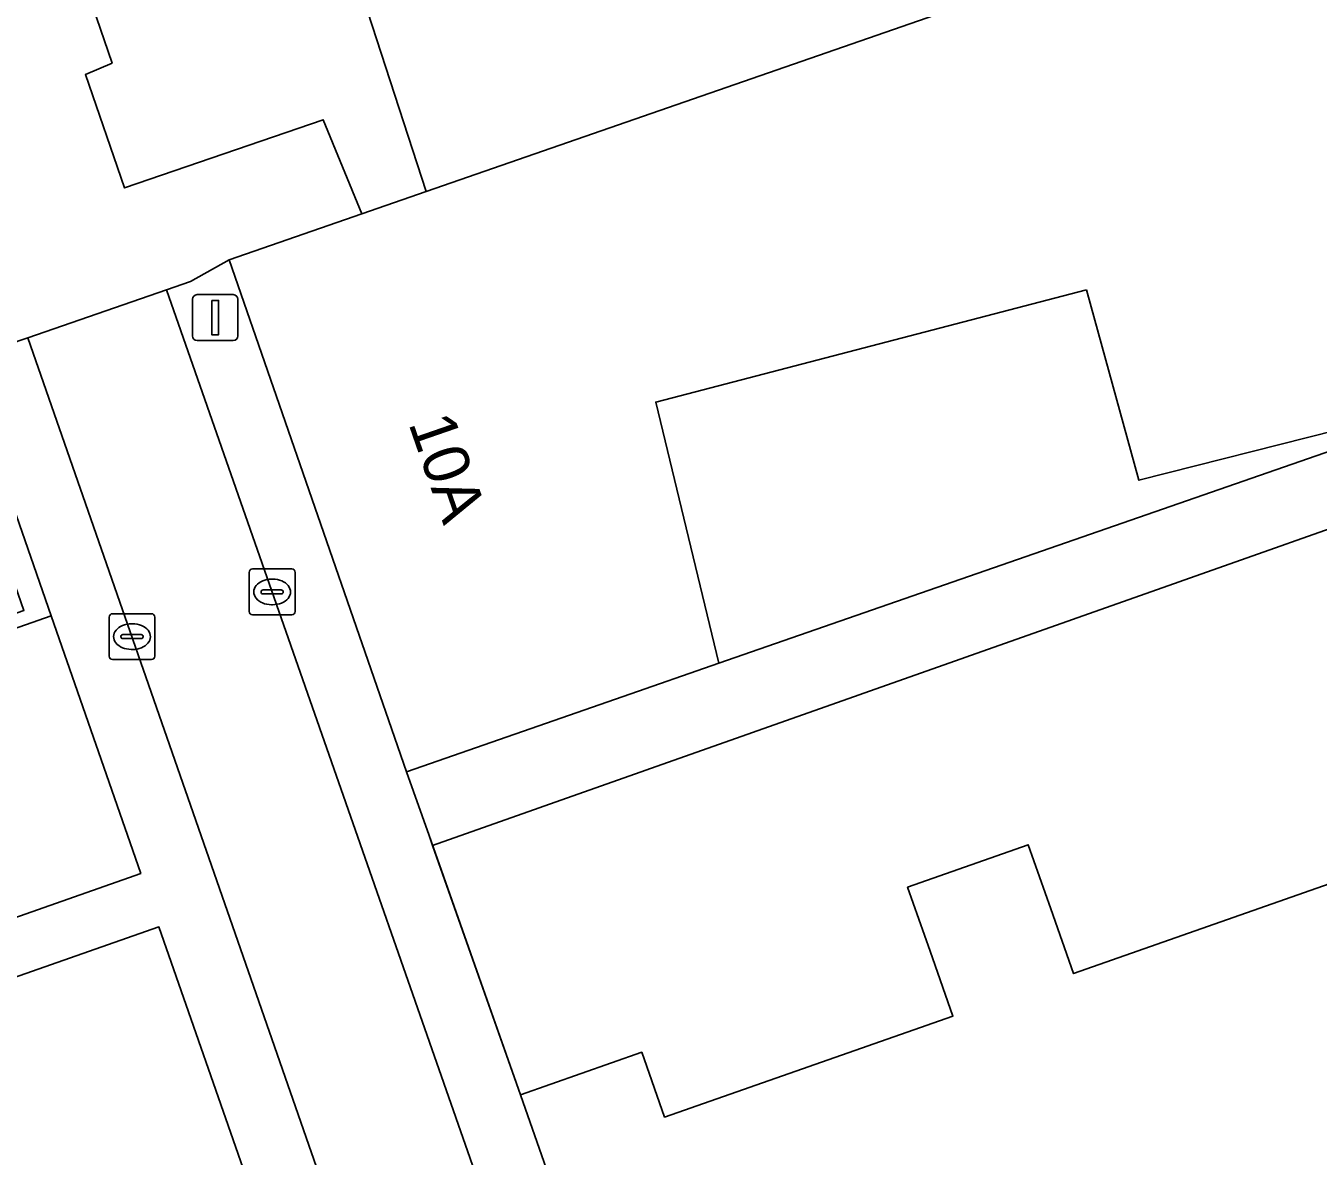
# Model space of a CAD drawing. Extents: x 159371 to 159986, y 382987 to 383597.
# Drawn here: x 159635.1 to 159663.28, y 383315.4 to 383340.04 of the extents above; entities that cross this region are included whole.
import ezdxf

# ---------------------------------------------------------------- set-up
doc = ezdxf.new("R2010")
doc.units = 0
for name, color, linetype in [('IMGEO_Erf', 7, 'Continuous'), ('IMGEO_Groenvoorziening', 7, 'Continuous'), ('IMGEO_Kolk', 7, 'Continuous'), ('IMGEO_Lichtmast', 7, 'Continuous'), ('IMGEO_Muur', 7, 'Continuous'), ('IMGEO_Pand', 7, 'Continuous'), ('IMGEO_Pand_nummerreeks', 7, 'Continuous'), ('IMGEO_Rijbaan_lokaal_open', 7, 'Continuous'), ('IMGEO_Terreindeel_gesloten', 7, 'Continuous'), ('IMGEO_Voetpad_open', 7, 'Continuous')]:
    doc.layers.add(name, color=color, linetype=linetype)

msp = doc.modelspace()

# ---------------------------------------------------------------- linework, layer by layer
at = {"layer": 'IMGEO_Erf'}
for points in [[(159681.296, 383335.353), (159643.966, 383322.174), (159645.886, 383316.734), (159648.529, 383317.662), (159649.026, 383316.247), (159655.31, 383318.452), (159654.813, 383319.867), (159654.323, 383321.261), (159656.956, 383322.186), (159657.446, 383320.791), (159657.943, 383319.376), (159664.368, 383321.63)], [(159633.525, 383310.811), (159640.34, 383313.197), (159639.844, 383314.612), (159639.998, 383314.666), (159638.001, 383320.394), (159611.994, 383311.273)]]:
    msp.add_lwpolyline(points, dxfattribs=at)
msp.add_lwpolyline([(159658.222, 383334.284), (159648.831, 383331.841), (159650.209, 383326.145), (159667.985, 383332.318), (159659.367, 383330.135)], close=True, dxfattribs=at)
at = {"layer": 'IMGEO_Groenvoorziening'}
msp.add_lwpolyline([(159634.849, 383345.441), (159636.979, 383339.231), (159636.397, 383338.982), (159637.249, 383336.509), (159641.583, 383337.997), (159642.421, 383335.945), (159643.825, 383336.433), (159639.809, 383348.793), (159650.451, 383352.464), (159648.673, 383358.7), (159660.333, 383361.889), (159659.23, 383366.272), (159646.569, 383362.986), (159645.066, 383369.122), (159646.091, 383369.372), (159643.576, 383379.146), (159638.181, 383377.778), (159637.233, 383377.7), (159639.388, 383369.792), (159627.787, 383366.742)], dxfattribs=at)
at = {"layer": 'IMGEO_Kolk'}
for p, q in [((159640.043, 383328.2), (159640.895, 383328.2)), ((159639.968, 383327.274), (159639.968, 383328.126)), ((159640.456, 383327.98), (159640.481, 383327.98)), ((159640.969, 383328.126), (159640.969, 383327.274)), ((159640.227, 383327.694), (159640.227, 383327.706)), ((159640.665, 383327.657), (159640.267, 383327.657)), ((159640.27, 383327.743), (159640.668, 383327.743)), ((159640.711, 383327.706), (159640.711, 383327.694)), ((159640.479, 383327.42), (159640.454, 383327.42)), ((159636.912, 383326.299), (159636.912, 383327.151)), ((159636.987, 383327.225), (159637.839, 383327.225)), ((159637.913, 383327.151), (159637.913, 383326.299)), ((159640.895, 383327.2), (159640.043, 383327.2)), ((159637.214, 383326.768), (159637.612, 383326.768)), ((159637.4, 383327.005), (159637.425, 383327.005)), ((159637.171, 383326.719), (159637.171, 383326.731)), ((159637.609, 383326.682), (159637.211, 383326.682)), ((159637.655, 383326.731), (159637.655, 383326.719)), ((159637.839, 383326.225), (159636.987, 383326.225)), ((159637.423, 383326.445), (159637.398, 383326.445))]:
    msp.add_line(p, q, dxfattribs=at)
for points in [[(159640.043, 383328.2), (159640.895, 383328.2)], [(159639.968, 383327.274), (159639.968, 383328.126)], [(159640.969, 383328.126), (159640.969, 383327.274)], [(159636.912, 383326.299), (159636.912, 383327.151)], [(159636.987, 383327.225), (159637.839, 383327.225)], [(159637.913, 383327.151), (159637.913, 383326.299)], [(159640.895, 383327.2), (159640.043, 383327.2)], [(159637.839, 383326.225), (159636.987, 383326.225)]]:
    msp.add_lwpolyline(points, dxfattribs=at)
for centre, radius, start, end in [((159640.045, 383328.124), 0.0765, 91.552, 178.448), ((159640.045, 383328.124), 0.0765, 91.552, 178.448), ((159640.893, 383328.124), 0.0765, 1.552, 88.448), ((159640.893, 383328.124), 0.0765, 1.552, 88.448), ((159640.267, 383327.703), 0.0403, 85.8775, 175.7526), ((159640.264, 383327.693), 0.0366, 178.938, 274.7102), ((159640.668, 383327.7), 0.043, 264.8664, 352.4533), ((159640.672, 383327.705), 0.0386, 1.7309, 96.639), ((159636.989, 383327.149), 0.0765, 91.552, 178.448), ((159636.989, 383327.149), 0.0765, 91.552, 178.448), ((159637.837, 383327.149), 0.0765, 1.552, 88.448), ((159637.837, 383327.149), 0.0765, 1.552, 88.448), ((159640.045, 383327.276), 0.0765, 181.552, 268.448), ((159640.045, 383327.276), 0.0765, 181.552, 268.448), ((159640.893, 383327.276), 0.0765, 271.552, 358.448), ((159640.893, 383327.276), 0.0765, 271.552, 358.448), ((159637.211, 383326.728), 0.0403, 85.8775, 175.7526), ((159637.616, 383326.73), 0.0386, 1.7309, 96.639), ((159637.208, 383326.718), 0.0366, 178.938, 274.7102), ((159637.612, 383326.725), 0.043, 264.8664, 352.4533), ((159636.989, 383326.301), 0.0765, 181.552, 268.448), ((159636.989, 383326.301), 0.0765, 181.552, 268.448), ((159637.837, 383326.301), 0.0765, 271.552, 358.448), ((159637.837, 383326.301), 0.0765, 271.552, 358.448)]:
    msp.add_arc(centre, radius, start, end, dxfattribs=at)
for centre, major_axis, ratio, start_param, end_param in [((159640.455, 383327.7), (-0.387, 0.002), 0.722429, 4.712389, 7.853982), ((159640.48, 383327.7), (-0.39, 0.002), 0.717154, 1.570796, 4.712389), ((159637.399, 383326.725), (-0.387, 0.002), 0.722429, 4.712389, 7.853982), ((159637.424, 383326.725), (-0.39, 0.002), 0.717154, 1.570796, 4.712389)]:
    msp.add_ellipse(centre, major_axis=major_axis, ratio=ratio, start_param=start_param, end_param=end_param, dxfattribs=at)
at = {"layer": 'IMGEO_Lichtmast'}
for p, q in [((159638.732, 383333.282), (159638.732, 383334.082)), ((159638.732, 383334.082), (159638.732, 383333.282)), ((159638.832, 383334.182), (159639.622, 383334.182)), ((159639.622, 383334.182), (159638.832, 383334.182)), ((159639.722, 383334.082), (159639.722, 383333.282)), ((159639.722, 383333.282), (159639.722, 383334.082)), ((159639.622, 383333.182), (159638.832, 383333.182)), ((159638.832, 383333.182), (159639.622, 383333.182))]:
    msp.add_line(p, q, dxfattribs=at)
msp.add_lwpolyline([(159639.152, 383334.057), (159639.302, 383334.057), (159639.302, 383333.307), (159639.152, 383333.307), (159639.152, 383334.057)], dxfattribs=at)
for centre, start, end in [((159638.832, 383334.082), 90, 180), ((159638.832, 383334.082), 90, 180), ((159639.622, 383334.082), 0, 90), ((159639.622, 383334.082), 360, 90), ((159638.832, 383333.282), 180, 270), ((159638.832, 383333.282), 180, 270), ((159639.622, 383333.282), 270, 0), ((159639.622, 383333.282), 270, 0)]:
    msp.add_arc(centre, 0.1, start, end, dxfattribs=at)
at = {"layer": 'IMGEO_Muur'}
for points in [[(159645.886, 383316.734), (159643.889, 383322.392)], [(159638.001, 383320.394), (159639.998, 383314.666)]]:
    msp.add_lwpolyline(points, dxfattribs=at)
at = {"layer": 'IMGEO_Pand'}
msp.add_lwpolyline([(159658.222, 383334.284), (159659.367, 383330.135), (159667.985, 383332.318), (159665.023, 383343.791), (159664.897, 383343.747), (159656.195, 383340.726), (159643.825, 383336.433), (159642.421, 383335.945), (159639.534, 383334.943), (159643.399, 383323.78), (159648.123, 383325.421), (159650.209, 383326.145), (159648.831, 383331.841)], close=True, dxfattribs=at)
msp.add_lwpolyline([(159664.368, 383321.63), (159657.943, 383319.376), (159657.446, 383320.791), (159656.956, 383322.186), (159654.323, 383321.261), (159654.813, 383319.867), (159655.31, 383318.452), (159649.026, 383316.247), (159648.529, 383317.662), (159645.886, 383316.734), (159649.218, 383307.194)], dxfattribs=at)
at = {"layer": 'IMGEO_Rijbaan_lokaal_open'}
for points in [[(159638.165, 383334.29), (159635.142, 383333.243), (159644.757, 383305.615), (159648.011, 383306.048), (159647.812, 383306.694)], [(159637.605, 383321.561), (159635.65, 383327.182), (159629.365, 383324.977), (159610.898, 383318.498), (159612.758, 383312.821)]]:
    msp.add_lwpolyline(points, close=True, dxfattribs=at)
at = {"layer": 'IMGEO_Terreindeel_gesloten'}
msp.add_lwpolyline([(159653.87, 383347.749), (159652.119, 383353.038), (159650.451, 383352.464), (159639.809, 383348.793), (159643.825, 383336.433), (159656.195, 383340.726)], close=True, dxfattribs=at)
at = {"layer": 'IMGEO_Voetpad_open'}
for points in [[(159634.69, 383333.087), (159635.142, 383333.243), (159638.165, 383334.29), (159638.685, 383334.47), (159639.534, 383334.943), (159642.421, 383335.945), (159641.583, 383337.997), (159637.249, 383336.509), (159636.397, 383338.982), (159636.979, 383339.231), (159634.849, 383345.441)], [(159667.985, 383332.318), (159650.209, 383326.145), (159648.123, 383325.421), (159643.399, 383323.78), (159643.889, 383322.392), (159643.966, 383322.174), (159681.296, 383335.353)]]:
    msp.add_lwpolyline(points, dxfattribs=at)
for points in [[(159645.886, 383316.734), (159643.966, 383322.174), (159643.889, 383322.392), (159643.399, 383323.78), (159639.534, 383334.943), (159638.685, 383334.47), (159638.165, 383334.29), (159647.812, 383306.694), (159649.218, 383307.194)], [(159635.142, 383333.243), (159634.69, 383333.087), (159633.682, 383332.842), (159635.65, 383327.182), (159637.605, 383321.561), (159612.758, 383312.821), (159610.898, 383318.498), (159609.052, 383324.122), (159607.877, 383323.724), (159609.788, 383317.937), (159611.905, 383311.499), (159611.994, 383311.273), (159638.001, 383320.394), (159639.998, 383314.666), (159643.318, 383305.13), (159644.757, 383305.615)], [(159633.686, 383331.211), (159635.055, 383327.298), (159629.263, 383325.268), (159629.365, 383324.977), (159635.65, 383327.182), (159633.682, 383332.842), (159633.187, 383332.647), (159627.409, 383330.63), (159627.915, 383329.182)]]:
    msp.add_lwpolyline(points, close=True, dxfattribs=at)

# ---------------------------------------------------------------- texts
at = {"layer": 'IMGEO_Pand_nummerreeks'}
msp.add_text('10A', height=1, rotation=289.0965, dxfattribs=at).set_placement((159643.434, 383331.381))

doc.saveas('drawing.dxf')
